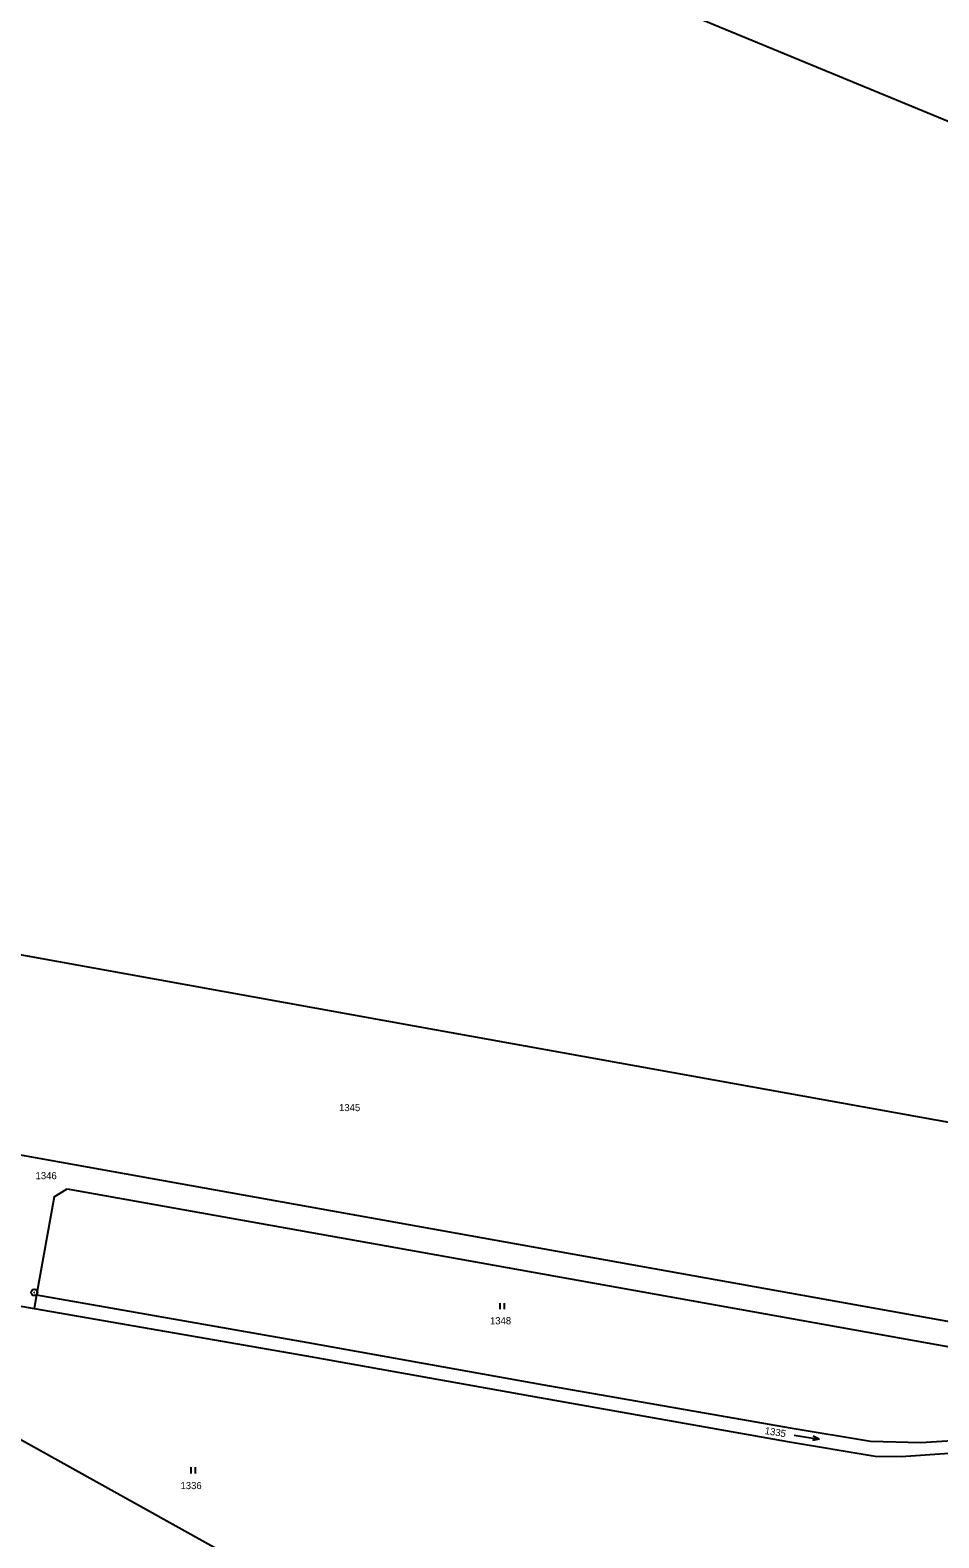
# Model space of a CAD drawing. Extents: x -796130 to -793145, y -1109506 to -1106267.
# Drawn here: x -795382.3 to -795165.2, y -1107731.2 to -1107371.1 of the extents above; entities that cross this region are included whole.
import ezdxf

# ---------------------------------------------------------------- set-up
doc = ezdxf.new("R2010")
doc.units = 0
for name, color, linetype in [('Vrstva 1', 7, 'Continuous'), ('Vrstva 12', 7, 'Continuous'), ('Vrstva 14', 7, 'Continuous'), ('Vrstva 23', 7, 'Continuous'), ('Vrstva 28', 7, 'Continuous')]:
    doc.layers.add(name, color=color, linetype=linetype)

msp = doc.modelspace()

# ---------------------------------------------------------------- linework, layer by layer
at = {"layer": 'Vrstva 1'}
for p, q in [((-795308.61, -1107332.64), (-795158.99, -1107394.55)), ((-795290.5, -1107608.97), (-795481.44, -1107574.51)), ((-795115.49, -1107640.57), (-795290.5, -1107608.97)), ((-795460.68, -1107626.06), (-795312.81, -1107652.58)), ((-795376.57, -1107649.78), (-795380.76, -1107673.17)), ((-795376.57, -1107649.78), (-795373.44, -1107647.82)), ((-795373.44, -1107647.82), (-795283.03, -1107664.03)), ((-795312.81, -1107652.58), (-795159.16, -1107680.14)), ((-795283.03, -1107664.03), (-795159.63, -1107686.15)), ((-795387.25, -1107675.39), (-795381.34, -1107676.43)), ((-795380.76, -1107673.17), (-795381.34, -1107676.43)), ((-795381.34, -1107676.43), (-795316.29, -1107687.71)), ((-795380.76, -1107673.17), (-795315.97, -1107684.5)), ((-795315.97, -1107684.5), (-795259.59, -1107694.68)), ((-795316.29, -1107687.71), (-795260.65, -1107697.69)), ((-795260.65, -1107697.69), (-795201.4, -1107708.16)), ((-795259.59, -1107694.68), (-795200.78, -1107704.9)), ((-795200.78, -1107704.9), (-795181.54, -1107708.07)), ((-795201.4, -1107708.16), (-795180.45, -1107711.65)), ((-795181.54, -1107708.07), (-795169.54, -1107708.39)), ((-795174.26, -1107711.73), (-795083.2, -1107705.59)), ((-795169.54, -1107708.39), (-795138.32, -1107706.38)), ((-795180.45, -1107711.65), (-795174.26, -1107711.73))]:
    msp.add_line(p, q, dxfattribs=at)
at = {"layer": 'Vrstva 12'}
msp.add_line((-795427.31, -1107683.94), (-795330.63, -1107737.7), dxfattribs=at)
at = {"layer": 'Vrstva 23'}
for p, q in [((-795270.05, -1107676.61), (-795270.05, -1107675.11)), ((-795269.05, -1107675.11), (-795269.05, -1107676.61)), ((-795199.791, -1107706.698), (-795193.868, -1107707.661)), ((-795193.868, -1107707.661), (-795195.429, -1107707.914)), ((-795193.868, -1107707.661), (-795195.269, -1107706.927)), ((-795343.86, -1107715.83), (-795343.86, -1107714.33)), ((-795342.86, -1107714.33), (-795342.86, -1107715.83))]:
    msp.add_line(p, q, dxfattribs=at)
at = {"layer": 'Vrstva 28'}
for radius in [0.75, 0.01]:
    msp.add_circle((-795381.3, -1107672.59), radius, dxfattribs=at)

# ---------------------------------------------------------------- texts
at = {"layer": 'Vrstva 14'}
for s, p in [('1345', (-795308.502, -1107629.28)), ('1346', (-795380.996, -1107645.54)), ('1348', (-795272.466, -1107680.19)), ('1336', (-795346.38, -1107719.56))]:
    msp.add_text(s, height=1.7, dxfattribs=at).set_placement(p)
msp.add_text('1335', height=1.7, rotation=351, dxfattribs=at).set_placement((-795206.915, -1107706.386))

doc.saveas('drawing.dxf')
